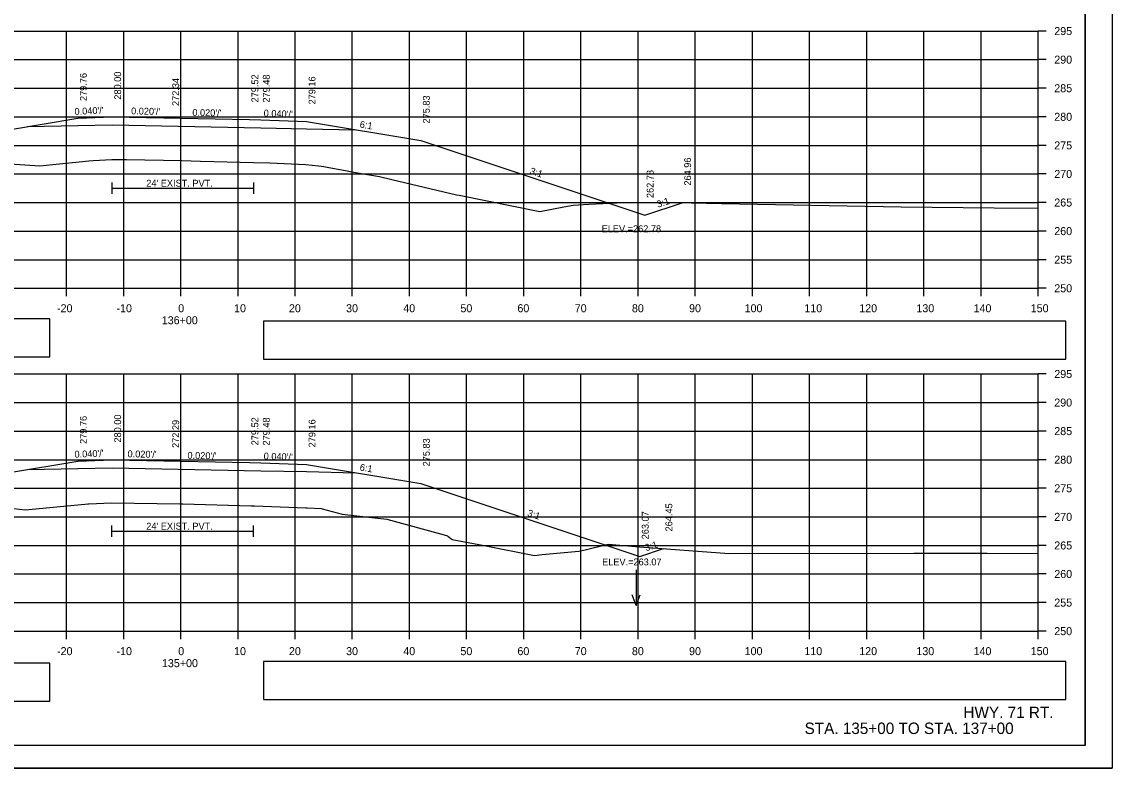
# Model space of a CAD drawing. Extents: x 285 to 4233, y -659 to 3710.
# Drawn here: x 2531.7 to 2722.4, y 2109.5 to 2240.2 of the extents above; entities that cross this region are included whole.
import ezdxf

# ---------------------------------------------------------------- set-up
doc = ezdxf.new("R2010")
doc.units = 0
for name, color, linetype in [('R_Alt Surface', 7, 'Continuous'), ('R_Axis', 7, 'Continuous'), ('R_Axis Annot', 7, 'Continuous'), ('R_Border', 7, 'Continuous'), ('R_Draft', 7, 'Continuous'), ('R_Exist Surface', 7, 'Continuous'), ('R_Fin Surface', 7, 'Continuous'), ('R_Grid', 7, 'Continuous'), ('R_No Plot', 7, 'Continuous'), ('R_Water', 7, 'Continuous'), ('R_Water Annot', 7, 'Continuous'), ('R_Xsect Elev', 7, 'Continuous'), ('R_Xsect Slope', 7, 'Continuous')]:
    doc.layers.add(name, color=color, linetype=linetype)

msp = doc.modelspace()

# ---------------------------------------------------------------- linework, layer by layer
at = {"layer": 'R_Alt Surface'}
for points in [[(2532.66, 2221.82), (2541.5, 2222), (2547.5, 2222.12), (2547.5, 2222.12), (2573.5, 2221.6), (2581.5, 2221.44), (2590.07, 2221.26)], [(2532.66, 2221.82), (2541.5, 2222), (2547.5, 2222.12), (2547.5, 2222.12), (2573.5, 2221.6), (2581.5, 2221.44), (2590.07, 2221.26)], [(2532.66, 2221.82), (2541.5, 2222), (2547.5, 2222.12), (2547.5, 2222.12), (2573.5, 2221.6), (2581.5, 2221.44), (2590.07, 2221.26)], [(2547.45, 2212.06), (2547.45, 2210.06)], [(2547.45, 2211.06), (2572.23, 2211.06)], [(2572.23, 2212.06), (2572.23, 2210.06)], [(2532.66, 2161.82), (2541.5, 2162), (2547.5, 2162.12), (2547.5, 2162.12), (2573.5, 2161.6), (2581.5, 2161.44), (2590.07, 2161.26)], [(2547.37, 2152.01), (2547.37, 2150.01)], [(2572.16, 2152.01), (2572.16, 2150.01)], [(2547.37, 2151.01), (2572.16, 2151.01)]]:
    msp.add_lwpolyline(points, dxfattribs=at)
at = {"layer": 'R_Axis'}
for p, q in [((2709.5, 2193.53), (2709.5, 2238.53)), ((2710.9, 2238.53), (2709.5, 2238.53)), ((2710.9, 2233.53), (2709.5, 2233.53)), ((2710.9, 2228.53), (2709.5, 2228.53)), ((2710.9, 2223.53), (2709.5, 2223.53)), ((2710.9, 2218.53), (2709.5, 2218.53)), ((2710.9, 2213.53), (2709.5, 2213.53)), ((2710.9, 2208.53), (2709.5, 2208.53)), ((2710.9, 2203.53), (2709.5, 2203.53)), ((2710.9, 2198.53), (2709.5, 2198.53)), ((2409.5, 2193.53), (2709.5, 2193.53)), ((2539.5, 2192.13), (2539.5, 2193.53)), ((2549.5, 2192.13), (2549.5, 2193.53)), ((2559.5, 2192.13), (2559.5, 2193.53)), ((2569.5, 2192.13), (2569.5, 2193.53)), ((2579.5, 2192.13), (2579.5, 2193.53)), ((2589.5, 2192.13), (2589.5, 2193.53)), ((2599.5, 2192.13), (2599.5, 2193.53)), ((2609.5, 2192.13), (2609.5, 2193.53)), ((2619.5, 2192.13), (2619.5, 2193.53)), ((2629.5, 2192.13), (2629.5, 2193.53)), ((2639.5, 2192.13), (2639.5, 2193.53)), ((2649.5, 2192.13), (2649.5, 2193.53)), ((2659.5, 2192.13), (2659.5, 2193.53)), ((2669.5, 2192.13), (2669.5, 2193.53)), ((2679.5, 2192.13), (2679.5, 2193.53)), ((2689.5, 2192.13), (2689.5, 2193.53)), ((2699.5, 2192.13), (2699.5, 2193.53)), ((2709.5, 2192.13), (2709.5, 2193.53)), ((2710.9, 2193.53), (2709.5, 2193.53)), ((2709.5, 2133.53), (2709.5, 2178.53)), ((2710.9, 2178.53), (2709.5, 2178.53)), ((2710.9, 2173.53), (2709.5, 2173.53)), ((2710.9, 2168.53), (2709.5, 2168.53)), ((2710.9, 2163.53), (2709.5, 2163.53)), ((2710.9, 2158.53), (2709.5, 2158.53)), ((2710.9, 2153.53), (2709.5, 2153.53)), ((2710.9, 2148.53), (2709.5, 2148.53)), ((2710.9, 2143.53), (2709.5, 2143.53)), ((2710.9, 2138.53), (2709.5, 2138.53)), ((2409.5, 2133.53), (2709.5, 2133.53)), ((2539.5, 2132.13), (2539.5, 2133.53)), ((2549.5, 2132.13), (2549.5, 2133.53)), ((2559.5, 2132.13), (2559.5, 2133.53)), ((2569.5, 2132.13), (2569.5, 2133.53)), ((2579.5, 2132.13), (2579.5, 2133.53)), ((2589.5, 2132.13), (2589.5, 2133.53)), ((2599.5, 2132.13), (2599.5, 2133.53)), ((2609.5, 2132.13), (2609.5, 2133.53)), ((2619.5, 2132.13), (2619.5, 2133.53)), ((2629.5, 2132.13), (2629.5, 2133.53)), ((2639.5, 2132.13), (2639.5, 2133.53)), ((2649.5, 2132.13), (2649.5, 2133.53)), ((2659.5, 2132.13), (2659.5, 2133.53)), ((2669.5, 2132.13), (2669.5, 2133.53)), ((2679.5, 2132.13), (2679.5, 2133.53)), ((2689.5, 2132.13), (2689.5, 2133.53)), ((2699.5, 2132.13), (2699.5, 2133.53)), ((2709.5, 2132.13), (2709.5, 2133.53)), ((2710.9, 2133.53), (2709.5, 2133.53))]:
    msp.add_line(p, q, dxfattribs=at)
at = {"layer": 'R_Axis Annot'}
for points in [[(2408.87, 2181.52), (2536.56, 2181.52), (2536.56, 2188.18), (2408.87, 2188.18)], [(2573.96, 2181.1), (2714.32, 2181.1), (2714.32, 2187.75), (2573.96, 2187.75)], [(2408.87, 2121.28), (2536.56, 2121.28), (2536.56, 2127.94), (2408.87, 2127.94)], [(2573.96, 2121.55), (2714.32, 2121.55), (2714.32, 2128.2), (2573.96, 2128.2)]]:
    msp.add_lwpolyline(points, close=True, dxfattribs=at)
at = {"layer": 'R_Border'}
for q in [(2717.68, 2318.99), (2401.5, 2113.53)]:
    msp.add_line((2717.68, 2113.53), q, dxfattribs=at)
at = {"layer": 'R_Exist Surface'}
for points in [[(2529.58, 2215.29), (2534.84, 2214.95), (2541.71, 2215.66), (2543.39, 2215.82), (2544.17, 2215.87), (2547.45, 2216.06), (2549.97, 2216.03), (2559.7, 2215.87), (2562.91, 2215.79), (2572.23, 2215.56), (2575.08, 2215.45), (2581.39, 2215.18), (2583.61, 2214.93), (2584.49, 2214.84), (2585.4, 2214.66), (2588.3, 2214.14), (2590.05, 2213.81), (2593.54, 2213.22), (2594.27, 2213.1), (2596.42, 2212.58), (2607.74, 2209.89), (2608.21, 2209.8), (2622.28, 2206.97), (2626.5, 2207.79), (2628.16, 2208.09), (2630.86, 2208.25), (2637.08, 2208.55), (2646.15, 2208.52), (2654.08, 2208.35), (2685.49, 2207.78), (2701.79, 2207.58), (2709.5, 2207.55)], [(2529.3, 2155.09), (2532.24, 2154.73), (2542.73, 2155.75), (2543.22, 2155.8), (2543.4, 2155.8), (2547.37, 2156.01), (2559.3, 2155.82), (2559.82, 2155.82), (2571.83, 2155.47), (2572.16, 2155.46), (2572.39, 2155.45), (2581.37, 2155.12), (2581.57, 2155.12), (2584.08, 2154.98), (2584.23, 2154.94), (2587.71, 2153.98), (2589.24, 2153.8), (2595.52, 2153.1), (2605.57, 2150.36), (2606.14, 2150.21), (2606.19, 2150.16), (2606.96, 2149.58), (2612.55, 2148.5), (2621.38, 2146.78), (2622.7, 2146.93), (2629.1, 2147.53), (2630.26, 2147.73), (2634.28, 2148.73), (2639.73, 2148.31), (2655.42, 2147.09), (2687.74, 2147.15), (2700.55, 2147.17), (2709.5, 2147.1)]]:
    msp.add_lwpolyline(points, dxfattribs=at)
at = {"layer": 'R_Fin Surface'}
for points in [[(2469.09, 2215.26), (2487.25, 2209.21), (2517.5, 2219.29), (2541.5, 2223.29), (2547.5, 2223.53), (2571.5, 2223.05), (2573.5, 2223.01), (2581.5, 2222.69), (2601.5, 2219.36), (2640.65, 2206.31), (2647.21, 2208.49)], [(2481.45, 2156.47), (2495.24, 2151.87), (2517.5, 2159.29), (2541.5, 2163.29), (2547.5, 2163.53), (2571.5, 2163.05), (2573.5, 2163.01), (2581.5, 2162.69), (2601.5, 2159.36), (2639.79, 2146.6), (2643.93, 2147.98)]]:
    msp.add_lwpolyline(points, dxfattribs=at)
at = {"layer": 'R_Grid'}
for p, q in [((2409.5, 2238.53), (2709.5, 2238.53)), ((2539.5, 2193.53), (2539.5, 2238.53)), ((2549.5, 2193.53), (2549.5, 2238.53)), ((2559.5, 2193.53), (2559.5, 2238.53)), ((2569.5, 2193.53), (2569.5, 2238.53)), ((2579.5, 2193.53), (2579.5, 2238.53)), ((2589.5, 2193.53), (2589.5, 2238.53)), ((2599.5, 2193.53), (2599.5, 2238.53)), ((2609.5, 2193.53), (2609.5, 2238.53)), ((2619.5, 2193.53), (2619.5, 2238.53)), ((2629.5, 2193.53), (2629.5, 2238.53)), ((2639.5, 2193.53), (2639.5, 2238.53)), ((2649.5, 2193.53), (2649.5, 2238.53)), ((2659.5, 2193.53), (2659.5, 2238.53)), ((2669.5, 2193.53), (2669.5, 2238.53)), ((2679.5, 2193.53), (2679.5, 2238.53)), ((2689.5, 2193.53), (2689.5, 2238.53)), ((2699.5, 2193.53), (2699.5, 2238.53)), ((2709.5, 2193.53), (2709.5, 2238.53)), ((2409.5, 2233.53), (2709.5, 2233.53)), ((2409.5, 2228.53), (2709.5, 2228.53)), ((2409.5, 2223.53), (2709.5, 2223.53)), ((2409.5, 2218.53), (2709.5, 2218.53)), ((2409.5, 2213.53), (2709.5, 2213.53)), ((2409.5, 2208.53), (2709.5, 2208.53)), ((2409.5, 2203.53), (2709.5, 2203.53)), ((2409.5, 2198.53), (2709.5, 2198.53)), ((2409.5, 2193.53), (2709.5, 2193.53)), ((2409.5, 2178.53), (2709.5, 2178.53)), ((2539.5, 2133.53), (2539.5, 2178.53)), ((2549.5, 2133.53), (2549.5, 2178.53)), ((2559.5, 2133.53), (2559.5, 2178.53)), ((2569.5, 2133.53), (2569.5, 2178.53)), ((2579.5, 2133.53), (2579.5, 2178.53)), ((2589.5, 2133.53), (2589.5, 2178.53)), ((2599.5, 2133.53), (2599.5, 2178.53)), ((2609.5, 2133.53), (2609.5, 2178.53)), ((2619.5, 2133.53), (2619.5, 2178.53)), ((2629.5, 2133.53), (2629.5, 2178.53)), ((2639.5, 2133.53), (2639.5, 2178.53)), ((2649.5, 2133.53), (2649.5, 2178.53)), ((2659.5, 2133.53), (2659.5, 2178.53)), ((2669.5, 2133.53), (2669.5, 2178.53)), ((2679.5, 2133.53), (2679.5, 2178.53)), ((2689.5, 2133.53), (2689.5, 2178.53)), ((2699.5, 2133.53), (2699.5, 2178.53)), ((2709.5, 2133.53), (2709.5, 2178.53)), ((2409.5, 2173.53), (2709.5, 2173.53)), ((2409.5, 2168.53), (2709.5, 2168.53)), ((2409.5, 2163.53), (2709.5, 2163.53)), ((2409.5, 2158.53), (2709.5, 2158.53)), ((2409.5, 2153.53), (2709.5, 2153.53)), ((2409.5, 2148.53), (2709.5, 2148.53)), ((2409.5, 2143.53), (2709.5, 2143.53)), ((2409.5, 2138.53), (2709.5, 2138.53)), ((2409.5, 2133.53), (2709.5, 2133.53))]:
    msp.add_line(p, q, dxfattribs=at)
at = {"layer": 'R_No Plot'}
msp.add_line((2389.1, 2109.55), (2722.43, 2109.55), dxfattribs=at)
for points in [[(2389.09, 2322.89), (2722.43, 2322.89), (2722.43, 2109.55), (2389.09, 2109.55)], [(2635.42, 2318.99), (2655.04, 2318.99), (2655.04, 2309.11), (2671.15, 2309.11), (2694.35, 2309.11), (2694.47, 2280.96), (2717.68, 2280.96), (2717.68, 2113.53), (2401.5, 2113.53), (2401.5, 2318.99)]]:
    msp.add_lwpolyline(points, close=True, dxfattribs=at)
at = {"layer": 'R_Water Annot'}
for p, q in [((2639.16, 2144.27), (2639.16, 2137.99)), ((2639.16, 2137.99), (2638.46, 2139.91)), ((2639.16, 2137.99), (2639.86, 2139.91))]:
    msp.add_line(p, q, dxfattribs=at)
at = {"layer": 'R_Xsect Elev'}
for p, q in [((2559.5, 2215.87), (2559.5, 2231.97)), ((2559.5, 2155.82), (2559.5, 2171.62))]:
    msp.add_line(p, q, dxfattribs=at)

# ---------------------------------------------------------------- texts
at = {"layer": 'R_Axis Annot'}
for s, p in [('295', (2712.3, 2237.83)), ('290', (2712.3, 2232.83)), ('285', (2712.3, 2227.83)), ('280', (2712.3, 2222.83)), ('275', (2712.3, 2217.83)), ('270', (2712.3, 2212.83)), ('265', (2712.3, 2207.83)), ('260', (2712.3, 2202.83)), ('255', (2712.3, 2197.83)), ('250', (2712.3, 2192.83)), ('-20', (2537.84, 2189.33)), ('-10', (2548.24, 2189.33)), ('0', (2559.04, 2189.33)), ('10', (2568.81, 2189.33)), ('20', (2578.41, 2189.33)), ('30', (2588.41, 2189.33)), ('40', (2598.41, 2189.33)), ('50', (2608.41, 2189.33)), ('60', (2618.38, 2189.33)), ('70', (2628.41, 2189.33)), ('80', (2638.41, 2189.33)), ('90', (2648.41, 2189.33)), ('100', (2658.13, 2189.33)), ('110', (2668.58, 2189.33)), ('120', (2678.18, 2189.33)), ('130', (2688.18, 2189.33)), ('140', (2698.18, 2189.33)), ('150', (2708.18, 2189.33)), ('136+00', (2556.16, 2187.23)), ('295', (2712.3, 2177.83)), ('290', (2712.3, 2172.83)), ('285', (2712.3, 2167.83)), ('280', (2712.3, 2162.83)), ('275', (2712.3, 2157.83)), ('270', (2712.3, 2152.83)), ('265', (2712.3, 2147.83)), ('260', (2712.3, 2142.83)), ('255', (2712.3, 2137.83)), ('250', (2712.3, 2132.83)), ('-20', (2537.84, 2129.33)), ('-10', (2548.24, 2129.33)), ('0', (2559.04, 2129.33)), ('10', (2568.81, 2129.33)), ('20', (2578.41, 2129.33)), ('30', (2588.41, 2129.33)), ('40', (2598.41, 2129.33)), ('50', (2608.41, 2129.33)), ('60', (2618.38, 2129.33)), ('70', (2628.41, 2129.33)), ('80', (2638.41, 2129.33)), ('90', (2648.41, 2129.33)), ('100', (2658.13, 2129.33)), ('110', (2668.58, 2129.33)), ('120', (2678.18, 2129.33)), ('130', (2688.18, 2129.33)), ('140', (2698.18, 2129.33)), ('150', (2708.18, 2129.33)), ('135+00', (2556.19, 2127.23))]:
    msp.add_text(s, height=1.4, dxfattribs=at).set_placement(p)
at = {"layer": 'R_Draft'}
for s, p in [('HWY. 71 RT. ', (2696.41, 2118.32)), ('STA. 135+00 TO STA. 137+00', (2668.62, 2115.53))]:
    msp.add_text(s, height=2, dxfattribs=at).set_placement(p)
at = {"layer": 'R_Water'}
for p in [(2553.45, 2211.31), (2553.45, 2151.3)]:
    msp.add_text("24' EXIST. PVT.", height=1.2, dxfattribs=at).set_placement(p)
at = {"layer": 'R_Xsect Elev'}
for s, p in [('279.76', (2543.05, 2226.29)), ('280.00', (2549.05, 2226.53)), ('272.34', (2559.2, 2225.42)), ('279.52', (2573.05, 2226.05)), ('279.48', (2575.05, 2226.01)), ('279.16', (2583.05, 2225.69)), ('275.83', (2603.05, 2222.36)), ('264.96', (2648.76, 2211.49)), ('262.78', (2642.2, 2209.31)), ('279.76', (2543.05, 2166.29)), ('280.00', (2549.05, 2166.53)), ('279.52', (2573.05, 2166.05)), ('279.48', (2575.05, 2166.01)), ('272.29', (2559.2, 2165.59)), ('279.16', (2583.05, 2165.69)), ('275.83', (2603.05, 2162.36)), ('264.45', (2645.48, 2150.98)), ('263.07', (2641.34, 2149.6))]:
    msp.add_text(s, height=1.2, rotation=90, dxfattribs=at).set_placement(p)
for s, p in [('ELEV.=262.78', (2633.12, 2203.34)), ('ELEV.=263.07', (2633.2, 2145.04))]:
    msp.add_text(s, height=1.2, dxfattribs=at).set_placement(p)
at = {"layer": 'R_Xsect Slope'}
for s, rotation, p in [("0.040'/'", 2.2906, (2540.92, 2223.87)), ("0.020'/'", 358.8542, (2550.79, 2223.96)), ("0.020'/'", 358.8542, (2561.5, 2223.7)), ("0.040'/'", 357.7094, (2573.97, 2223.59)), ('6:1', 350.5377, (2590.73, 2221.66)), ('3:1', 341.5651, (2620.45, 2213.57)), ('3:1', 18.4349, (2642.99, 2207.61)), ("0.040'/'", 2.2906, (2540.92, 2163.87)), ("0.020'/'", 358.8542, (2550.17, 2163.96)), ("0.020'/'", 358.8542, (2560.65, 2163.7)), ("0.040'/'", 357.7094, (2573.97, 2163.59)), ('6:1', 350.5377, (2590.73, 2161.66)), ('3:1', 341.5651, (2620.01, 2153.72)), ('3:1', 18.4349, (2640.91, 2147.5))]:
    msp.add_text(s, height=1.2, rotation=rotation, dxfattribs=at).set_placement(p)

doc.saveas('drawing.dxf')
